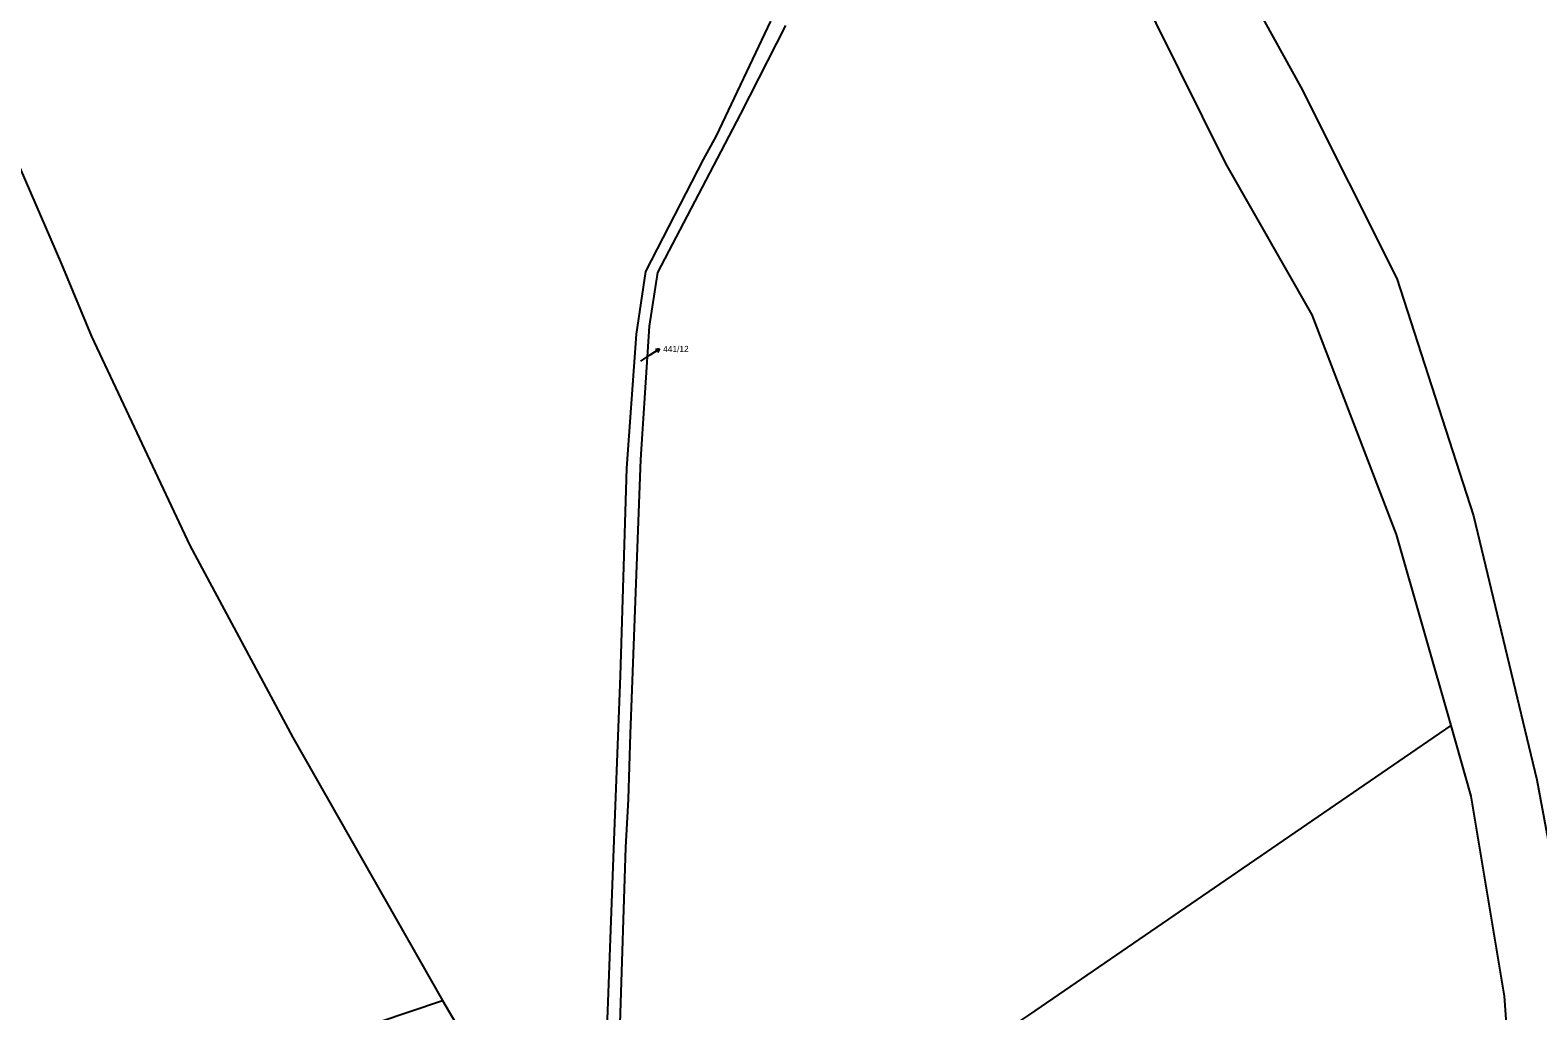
# Model space of a CAD drawing. Extents: x -880531 to -877616, y -1023932 to -1021350.
# Drawn here: x -879914.9 to -879503.7, y -1023198.6 to -1022931.1 of the extents above; entities that cross this region are included whole.
import ezdxf

# ---------------------------------------------------------------- set-up
doc = ezdxf.new("R2010")
doc.units = 0
for name, color, linetype in [('Hranice parcel', 7, 'Continuous'), ('Parcelní čísla', 7, 'Continuous'), ('Pop  PČ popisy', 7, 'Continuous')]:
    doc.layers.add(name, color=color, linetype=linetype)

msp = doc.modelspace()

# ---------------------------------------------------------------- linework, layer by layer
at = {"layer": 'Hranice parcel'}
for points in [[(-879527.34, -1023120.75), (-879542.22, -1023068.65), (-879565.2, -1023008.76), (-879588.79, -1022967.4), (-879620.45, -1022903.57), (-879641.51, -1022876.25), (-879675.88, -1022828.2)], [(-879629.68, -1022850.85), (-879599.95, -1022889.3), (-879568.31, -1022946.57), (-879542.1, -1022998.8), (-879521.22, -1023063.57), (-879503.92, -1023135.64), (-879493.69, -1023190.7), (-879490.49, -1023230.91), (-879486.76, -1023264.58)], [(-879967.14, -1022885.22), (-879926.31, -1022949.08), (-879906.41, -1022994.89), (-879898.19, -1023014.67), (-879871.37, -1023071.65), (-879843.32, -1023124.08), (-879802.44, -1023195.78)], [(-879708.92, -1022929.76), (-879721.2, -1022953.88), (-879726.57, -1022964.2), (-879743.8, -1022997.19), (-879746.1, -1023011.86), (-879748.46, -1023048.19), (-879751.26, -1023123.02), (-879751.84, -1023140.9), (-879752.54, -1023154.07), (-879754.09, -1023202.09), (-879755.63, -1023240.59), (-879758.43, -1023259.5), (-879759.78, -1023261.27), (-879761.74, -1023260.17), (-879758.89, -1023240.26), (-879755.74, -1023154.38), (-879753.93, -1023107.21), (-879752.19, -1023050.58), (-879749.56, -1023013.98), (-879747.01, -1022996.88), (-879731.3, -1022966.33), (-879727.7, -1022959.9), (-879712.9, -1022928.63)], [(-880077.12, -1023065.31), (-880055.22, -1023067.87), (-880041.66, -1023106.22), (-880029.62, -1023146.23), (-880004.11, -1023215.22), (-879985.57, -1023257.44), (-879802.44, -1023195.78)], [(-879644.99, -1023201.47), (-879642.22, -1023199.58), (-879527.34, -1023120.75)], [(-879509.95, -1023291), (-879510.06, -1023232.76), (-879512.71, -1023194.62), (-879521.84, -1023140.03), (-879527.34, -1023120.75)], [(-879802.44, -1023195.78), (-879771.56, -1023248.4), (-879757.93, -1023279.39)]]:
    msp.add_lwpolyline(points, dxfattribs=at)
at = {"layer": 'Pop  PČ popisy'}
for p, q in [((-879745.78, -1023019.68), (-879743.263, -1023018.046)), ((-879743.263, -1023018.046), (-879744.376, -1023018.171)), ((-879743.263, -1023018.046), (-879743.83, -1023019.011)), ((-879748.33, -1023021.33), (-879745.78, -1023019.68))]:
    msp.add_line(p, q, dxfattribs=at)

# ---------------------------------------------------------------- texts
at = {"layer": 'Parcelní čísla'}
msp.add_text('441/12', height=1.7, dxfattribs=at).set_placement((-879742.26, -1023018.9))

doc.saveas('drawing.dxf')
